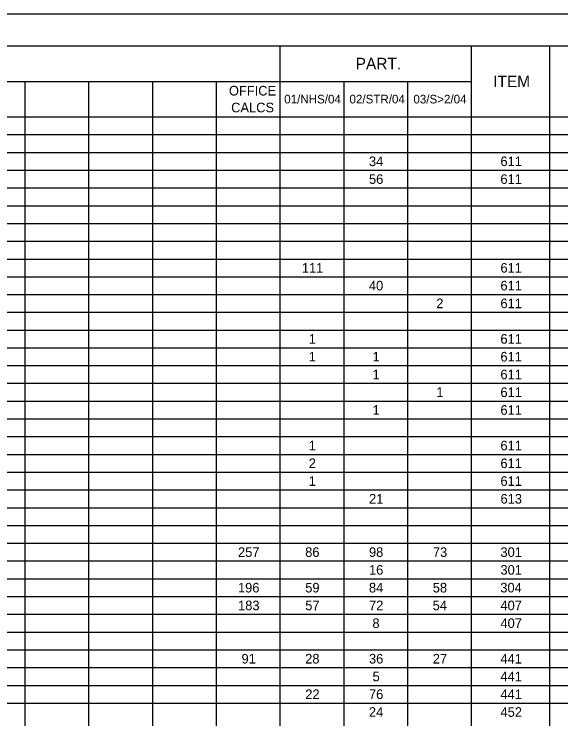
# Model space of a CAD drawing. Extents: x 0 to 34, y 0 to 22.
# Drawn here: x 8.36 to 16.98, y 10.89 to 22 of the extents above; entities that cross this region are included whole.
import ezdxf

# ---------------------------------------------------------------- set-up
doc = ezdxf.new("R2010")
doc.units = 0
for name, color, linetype in [('SH_Border', 7, 'Continuous'), ('SH_Cut_Line', 7, 'Continuous'), ('SH_Text', 7, 'Continuous')]:
    doc.layers.add(name, color=color, linetype=linetype)

msp = doc.modelspace()

# ---------------------------------------------------------------- linework, layer by layer
at = {"layer": 'SH_Border'}
msp.add_lwpolyline([(1.5, 21.5), (33.5, 21.5), (33.5, 0.5), (1.5, 0.5)], close=True, dxfattribs=at)
at = {"layer": 'SH_Cut_Line'}
msp.add_lwpolyline([(0, 0), (34, 0), (34, 22), (0, 22)], close=True, dxfattribs=at)
at = {"layer": 'SH_Text'}
for p, q in [((1.5, 21.5), (32, 21.5)), ((12.55, 21.5), (12.55, 0.502)), ((15.564, 21.5), (15.564, 0.502)), ((16.799, 21.5), (16.799, 0.502)), ((1.5, 20.94), (15.564, 20.94)), ((8.532, 20.94), (8.532, 0.502)), ((9.537, 20.94), (9.537, 0.502)), ((10.541, 20.94), (10.541, 0.502)), ((11.546, 20.94), (11.546, 0.502)), ((13.555, 20.94), (13.555, 0.502)), ((14.56, 20.94), (14.56, 0.502)), ((1.5, 20.38), (32, 20.38)), ((1.5, 20.1), (32, 20.1)), ((1.5, 19.82), (32, 19.82)), ((1.5, 19.54), (32, 19.54)), ((1.5, 19.26), (32, 19.26)), ((1.5, 18.98), (32, 18.98)), ((1.5, 18.7), (32, 18.7)), ((1.5, 18.42), (32, 18.42)), ((1.5, 18.14), (32, 18.14)), ((1.5, 17.86), (32, 17.86)), ((1.5, 17.58), (32, 17.58)), ((1.5, 17.3), (32, 17.3)), ((1.5, 17.021), (32, 17.021)), ((1.5, 16.741), (32, 16.741)), ((1.5, 16.461), (32, 16.461)), ((1.5, 16.181), (32, 16.181)), ((1.5, 15.901), (32, 15.901)), ((1.5, 15.621), (32, 15.621)), ((1.5, 15.341), (32, 15.341)), ((1.5, 15.061), (32, 15.061)), ((1.5, 14.781), (32, 14.781)), ((1.5, 14.501), (32, 14.501)), ((1.5, 14.221), (32, 14.221)), ((1.5, 13.941), (32, 13.941)), ((1.5, 13.661), (32, 13.661)), ((1.5, 13.381), (32, 13.381)), ((1.5, 13.101), (32, 13.101)), ((1.5, 12.821), (32, 12.821)), ((1.5, 12.541), (32, 12.541)), ((1.5, 12.261), (32, 12.261)), ((1.5, 11.981), (32, 11.981)), ((1.5, 11.701), (32, 11.701)), ((1.5, 11.421), (32, 11.421)), ((1.5, 11.141), (32, 11.141))]:
    msp.add_line(p, q, dxfattribs=at)

# ---------------------------------------------------------------- texts
for s, height, p in [('PART.', 0.1818, (13.744, 21.129)), ('ITEM', 0.1818, (15.91, 20.849)), ('OFFICE', 0.1515, (11.747, 20.717)), ('01/NHS/04', 0.1364, (12.618, 20.592)), ('02/STR/04', 0.1364, (13.646, 20.592)), ('03/S>2/04', 0.1364, (14.653, 20.592)), ('CALCS', 0.1515, (11.782, 20.452)), ('34', 0.1515, (13.952, 19.604)), ('611', 0.1515, (16.024, 19.604)), ('56', 0.1515, (13.953, 19.324)), ('611', 0.1515, (16.024, 19.324)), ('111', 0.1515, (12.895, 17.925)), ('611', 0.1515, (16.024, 17.925)), ('40', 0.1515, (13.952, 17.645)), ('611', 0.1515, (16.024, 17.645)), ('2', 0.152, (15.013, 17.365)), ('611', 0.1515, (16.024, 17.365)), ('1', 0.152, (13.004, 16.805)), ('611', 0.1515, (16.024, 16.805)), ('1', 0.152, (13.004, 16.525)), ('1', 0.152, (14.009, 16.525)), ('611', 0.1515, (16.024, 16.525)), ('1', 0.152, (14.009, 16.245)), ('611', 0.1515, (16.024, 16.245)), ('1', 0.152, (15.013, 15.965)), ('611', 0.1515, (16.024, 15.965)), ('1', 0.152, (14.009, 15.685)), ('611', 0.1515, (16.024, 15.685)), ('1', 0.152, (13.004, 15.125)), ('611', 0.1515, (16.024, 15.125)), ('2', 0.152, (13.004, 14.845)), ('611', 0.1515, (16.024, 14.845)), ('1', 0.152, (13.004, 14.565)), ('611', 0.1515, (16.024, 14.565)), ('21', 0.1515, (13.954, 14.285)), ('613', 0.1515, (16.025, 14.285)), ('257', 0.1515, (11.89, 13.445)), ('86', 0.1515, (12.948, 13.445)), ('98', 0.1515, (13.953, 13.445)), ('73', 0.1515, (14.96, 13.445)), ('301', 0.1515, (16.024, 13.445)), ('16', 0.1515, (13.953, 13.165)), ('301', 0.1515, (16.024, 13.165)), ('196', 0.1515, (11.889, 12.885)), ('59', 0.1515, (12.949, 12.885)), ('84', 0.1515, (13.952, 12.885)), ('58', 0.1515, (14.958, 12.885)), ('304', 0.1515, (16.022, 12.885)), ('183', 0.1515, (11.891, 12.605)), ('57', 0.1515, (12.949, 12.605)), ('72', 0.1515, (13.954, 12.605)), ('54', 0.1515, (14.956, 12.605)), ('407', 0.1515, (16.024, 12.605)), ('8', 0.152, (14.007, 12.325)), ('407', 0.1515, (16.024, 12.325)), ('91', 0.1515, (11.945, 11.765)), ('28', 0.1515, (12.948, 11.765)), ('36', 0.1515, (13.953, 11.765)), ('27', 0.1515, (14.958, 11.765)), ('441', 0.1515, (16.024, 11.765)), ('5', 0.152, (14.009, 11.485)), ('441', 0.1515, (16.024, 11.485)), ('22', 0.1515, (12.95, 11.205)), ('76', 0.1515, (13.953, 11.205)), ('441', 0.1515, (16.024, 11.205)), ('24', 0.1515, (13.952, 10.925)), ('452', 0.1515, (16.025, 10.925))]:
    msp.add_text(s, height=height, dxfattribs=at).set_placement(p)

doc.saveas('drawing.dxf')
